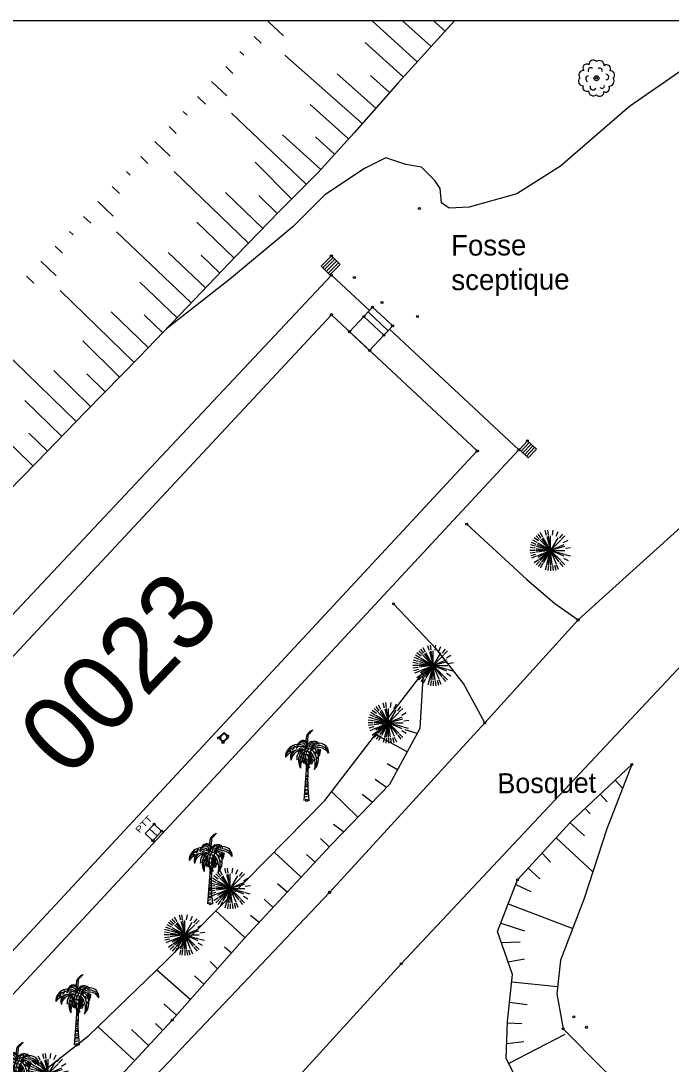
# Model space of a CAD drawing. Extents: x 344013 to 344423, y 298505 to 298795.
# Drawn here: x 344100.8 to 344132.3, y 298741.4 to 298791.9 of the extents above; entities that cross this region are included whole.
import ezdxf

# ---------------------------------------------------------------- set-up
doc = ezdxf.new("R2010")
doc.units = 0
for name, color, linetype in [('Default', 7, 'Continuous'), ('DH_CADRE -CARTOUCHE', 7, 'Continuous'), ('DH_CADRE-CARTOUCHE-NORD', 7, 'Continuous'), ('PC_CONCRETE', 7, 'Continuous'), ('PS_BOLT', 7, 'Continuous'), ('PS_CONST', 7, 'Continuous'), ('PS_DIM', 7, 'Continuous'), ('TOPO_COURBE NIVEAU', 7, 'Continuous'), ('TOPO_POINT', 7, 'Continuous'), ('TOPO_TALUS-TERRAIN NATUREL', 7, 'Continuous'), ('VOIRIE_BORDURE', 7, 'Continuous'), ('VOIRIE_ESPACE VERT', 7, 'Continuous')]:
    doc.layers.add(name, color=color, linetype=linetype)

# ---------------------------------------------------------------- blocks, each defined once
blk = doc.blocks.new('CT2')
at = {"layer": 'Default'}
blk.add_lwpolyline([(0, 0), (1, 0), (1, 1), (0, 1)], close=True, dxfattribs=at)
blk.add_lwpolyline([(0.5, 1), (0.5, 0)], dxfattribs=at)
blk.add_text('PTT', height=0.6, dxfattribs=at).set_placement((-0.3, 1.425))
blk = doc.blocks.new('REG_INC')
at = {"layer": 'Default'}
for p, q in [((0, 1), (1, 1)), ((0, 0), (0, 1)), ((1, 0), (0, 0)), ((1, 1), (1, 0))]:
    blk.add_line(p, q, dxfattribs=at)
for start, end in [(135.0055, 180.0055), (180.0066, 225.0066), (90.0058, 135.0058), (225.0069, 270.0069), (45.0069, 90.0069), (270.0058, 315.0058), (0.0066, 45.0066), (315.0055, 0.0055)]:
    blk.add_arc((0.5, 0.5), 0.44, start, end, dxfattribs=at)
blk = doc.blocks.new('R5')
at = {"layer": 'Default'}
for p, q in [((0, 1), (0, 0)), ((1, 1), (0, 1)), ((0.2, 1), (0.2, 0)), ((0.4, 1), (0.4, 0)), ((0.6, 1), (0.6, 0)), ((0.8, 1), (0.8, 0)), ((1, 0), (1, 1)), ((0, 0), (1, 0)), ((0.6, 0), (0.6, 0))]:
    blk.add_line(p, q, dxfattribs=at)
blk = doc.blocks.new('POINT_DISPLAY')
at = {"layer": 'Default'}
blk.add_circle((0, 0), 0.05, dxfattribs=at)
blk = doc.blocks.new('COCO')
at = {"layer": 'Default'}
for p, q in [((-0.037, 1.06), (0.056, 1.071)), ((0.058, 1.14), (-0.03, 1.162)), ((-0.026, 1.226), (0.061, 1.212)), ((-0.062, 0.537), (0.046, 0.552)), ((0.047, 0.655), (-0.058, 0.642)), ((-0.046, 0.891), (0.052, 0.927)), ((0.054, 0.998), (-0.041, 0.985)), ((0.046, 0.033), (-0.076, 0.051)), ((-0.073, 0.17), (0.045, 0.209)), ((0.045, 0.292), (-0.07, 0.288)), ((-0.068, 0.371), (0.045, 0.374)), ((0.045, 0.47), (-0.065, 0.453))]:
    blk.add_line(p, q, dxfattribs=at)
for points in [[(0.029, 2.551), (-0.016, 2.896), (0.002, 3.125), (0.059, 3.241), (0.173, 3.348), (0.189, 3.356), (0.282, 3.415), (0.266, 3.373), (0.2, 3.318), (0.143, 3.247), (0.093, 3.2), (0.081, 3.165), (0.057, 3.133), (0.057, 3.099), (0.06, 3.037), (0.039, 2.989), (0.039, 2.944), (0.049, 2.877), (0.037, 2.841), (0.013, 2.736)], [(-0.746, 2.559), (-0.864, 2.483)], [(-0.607, 2.534), (-0.704, 2.443)], [(-0.636, 2.639), (-0.541, 2.608)], [(-0.421, 2.58), (-0.503, 2.523)], [(-0.487, 2.68), (-0.386, 2.65)], [(-0.256, 2.553), (-0.385, 2.508)], [(0.013, 2.736), (0.036, 2.813), (0.046, 2.746)], [(0.133, 2.608), (0.185, 2.634)], [(0.196, 2.687), (0.323, 2.715)], [(0.283, 2.765), (0.331, 2.786)], [(-0.77, 2.413), (-0.836, 2.333)], [(-0.183, 2.493), (-0.348, 2.417), (-0.401, 2.307), (-0.448, 2.203), (-0.471, 2.086), (-0.474, 2.023), (-0.466, 1.973), (-0.455, 2.054), (-0.451, 2.146), (-0.387, 2.292), (-0.351, 2.354), (-0.284, 2.404), (-0.233, 2.445), (-0.012, 2.495)], [(-0.276, 2.151), (-0.329, 2.086)], [(-0.203, 2.314), (-0.274, 2.258)], [(-0.23, 2.152), (-0.237, 2.043)], [(-0.161, 2.218), (-0.158, 2.122)], [(-0.059, 2.024), (-0.083, 1.998)], [(-0.04, 2.247), (-0.081, 2.179)], [(0.015, 2.414), (-0.056, 2.352)], [(-0.025, 2.032), (0.002, 1.954)], [(0.022, 2.24), (0.043, 2.13)], [(0.081, 2.404), (0.106, 2.299)], [(0.385, 2.37), (0.469, 2.254)], [(0.473, 2.115), (0.509, 2.012)], [(-0.321, 1.997), (-0.364, 1.9)], [(-0.055, 0.716), (0.048, 0.717), (0.049, 0.787), (-0.051, 0.795)]]:
    blk.add_lwpolyline(points, dxfattribs=at)
for centre, radius in [((-0.144, 1.978), 0.0616), ((-0.187, 1.897), 0.0384), ((-0.124, 1.896), 0.0376), ((-0.11, 1.84), 0.0471), ((0.134, 1.862), 0.0549), ((0.208, 1.822), 0.0626), ((0.254, 1.938), 0.0628)]:
    blk.add_circle(centre, radius, dxfattribs=at)
for centre, radius, start, end in [((-0.427, 2.113), 0.595, 43.6121, 181.4625), ((-0.38, 1.964), 0.648, 57.9192, 166.6201), ((-0.123, 2.59), 0.323, 122.3475, 158.7636), ((-0.199, 2.618), 0.238, 4.5218, 154.101), ((-0.252, 2.556), 0.231, 4.2441, 134.2103), ((-0.16, 2.647), 0.255, 21.0861, 122.3475), ((0.376, 2.508), 0.372, 113.7681, 175.3309), ((0.376, 2.508), 0.372, 113.7681, 175.3309), ((0.418, 2.527), 0.326, 97.1248, 183.9512), ((1.025, 2.053), 0.958, 126.6858, 153.1664), ((0.59, 2.015), 0.548, 29.5654, 139.3517), ((-0.341, 1.9), 0.828, 46.9767, 50.1231), ((0.618, 2.316), 0.451, 356.1627, 159.0009), ((0.609, 2.187), 0.468, 12.1077, 148.3146), ((0.344, 2.407), 0.451, 69.0817, 104.862), ((-0.157, 2.027), 0.74, 51.2475, 54.5217), ((-1.005, 1.577), 1.786, 37.5668, 40.5156), ((-0.254, 2.28), 0.869, 28.4725, 37.0965), ((0.493, 2.767), 0.0679, 35.3205, 126.6858), ((-0.054, 2.379), 0.738, 25.8194, 35.3205), ((-0.291, 1.543), 0.918, 76.7389, 142.8025), ((-0.3, 2.12), 0.482, 151.1331, 199.5942), ((-0.196, 1.874), 0.565, 78.514, 171.3504), ((-0.32, 2.055), 0.433, 119.0834, 188.7621), ((0.362, 1.922), 0.754, 136.7113, 208.8221), ((0.551, 1.79), 0.879, 137.733, 194.3716), ((0.649, 1.599), 0.949, 145.5146, 182.4528), ((0.62, 2.159), 0.753, 153.0868, 230.1124), ((0.659, 2.068), 0.718, 142.3554, 222.2794), ((-0.007, 2.465), 0.0563, 81.7475, 144.3035), ((-0.189, 1.21), 1.324, 71.3715, 81.7475), ((0.294, 2.595), 0.256, 198.6765, 199.7627), ((0.963, 1.939), 0.9, 143.9866, 203.4288), ((0.544, 1.816), 0.474, 137.1953, 172.8987), ((0.308, 2.014), 0.226, 121.4297, 182.29), ((27.302, 0.106), 27.266, 175.4791, 176.5597), ((0.311, 2.152), 0.219, 141.856, 191.5175), ((0.372, 1.847), 0.277, 133.5956, 173.487), ((0.242, 1.964), 0.147, 110.9727, 165.9756), ((0.404, 1.878), 0.354, 125.0585, 146.3893), ((0.398, 2.098), 0.301, 136.4569, 162.0685), ((0.357, 2.084), 0.244, 133.1184, 172.7534), ((-0.759, 1.958), 0.922, 344.8505, 15.8988), ((-0.404, 2.045), 0.619, 329.4666, 26.6793), ((-0.289, 2.11), 0.564, 317.8279, 12.3386), ((-0.543, 1.744), 0.96, 344.8781, 41.1461), ((-0.341, 1.9), 0.828, 334.0687, 41.194), ((-0.157, 2.027), 0.74, 315.1472, 39.0239), ((-1.704, 1.849), 2.327, 7.5978, 16.3666), ((-0.254, 2.28), 0.869, 350.8883, 14.7063), ((-0.482, 2.552), 1.161, 339.3597, 356.5925), ((-85.428, 7.294), 85.622, 355.11326, 356.26352), ((-0.279, 1.637), 0.281, 2.1499, 36.6325), ((-0.265, 1.505), 0.316, 339.9997, 25.7228), ((0.199, 1.66), 0.176, 166.9443, 185.5966), ((0.808, 1.542), 0.777, 142.2358, 156.28)]:
    blk.add_arc(centre, radius, start, end, dxfattribs=at)
blk.add_ellipse((27.425, 0.272), major_axis=(-27.371, 0.966), ratio=0.529859, start_param=6.255729, end_param=6.369141, dxfattribs=at)
blk = doc.blocks.new('ARB1')
at = {"layer": 'Default'}
blk.add_circle((0, 0), 0.122, dxfattribs=at)
for centre, radius, start, end in [((-0.471, 0.503), 0.183, 53.9554, 222.2066), ((-0.153, 0.664), 0.211, 43.6925, 183.5969), ((0.139, 0.613), 0.241, 358.4583, 125.1928), ((0.501, 0.468), 0.183, 325.1444, 131.0175), ((-0.613, 0.139), 0.241, 88.4583, 215.1928), ((-0.373, -0.024), 0.149, 103.7092, 242.3465), ((-0.276, 0.37), 0.134, 52.4396, 209.5496), ((0.164, 0.38), 0.112, 330.5895, 133.7127), ((0.458, 0.052), 0.137, 276.6214, 88.967), ((0.613, -0.139), 0.241, 268.4583, 35.1928), ((0.664, 0.153), 0.211, 313.6925, 93.5969), ((-0.664, -0.153), 0.211, 133.6925, 273.5969), ((-0.478, -0.443), 0.19, 155.2243, 300.9377), ((-0.163, -0.42), 0.148, 159.5371, 338.1663), ((0.271, -0.38), 0.112, 210.5895, 13.7127), ((0.448, -0.483), 0.188, 243.1323, 33.0297), ((-0.139, -0.613), 0.241, 178.4583, 305.1928), ((0.153, -0.664), 0.211, 223.6925, 3.5969)]:
    blk.add_arc(centre, radius, start, end, dxfattribs=at)
blk = doc.blocks.new('ARB2')
at = {"layer": 'Default'}
for p, q in [((-0.575, 0.453), (-0.775, 0.605)), ((-0.513, 0.525), (-0.688, 0.702)), ((-0.438, 0.589), (-0.588, 0.786)), ((-0.356, 0.642), (-0.481, 0.858)), ((-0.181, 0.716), (-0.244, 0.956)), ((-0.088, 0.736), (-0.119, 0.983)), ((0.106, 0.736), (0.144, 0.983)), ((0.287, 0.684), (0.388, 0.914)), ((0.456, 0.589), (0.612, 0.786)), ((0.531, 0.525), (0.706, 0.702)), ((-0.731, 0), (-0.981, 0)), ((-0.725, 0.1), (-0.969, 0.133)), ((-0.706, 0.195), (-0.944, 0.259)), ((-0.675, 0.286), (-0.9, 0.381)), ((-0.631, 0.373), (-0.844, 0.497)), ((0.65, 0.373), (0.862, 0.497)), ((0.744, 0.1), (0.987, 0.133)), ((-0.725, -0.1), (-0.969, -0.133)), ((-0.706, -0.195), (-0.944, -0.259)), ((-0.675, -0.287), (-0.9, -0.383)), ((-0.575, -0.455), (-0.775, -0.605)), ((0.65, -0.373), (0.862, -0.498)), ((0.725, -0.195), (0.963, -0.259)), ((-0.513, -0.527), (-0.688, -0.702)), ((-0.438, -0.591), (-0.588, -0.787)), ((-0.356, -0.644), (-0.481, -0.859)), ((-0.181, -0.717), (-0.244, -0.956)), ((-0.088, -0.737), (-0.119, -0.983)), ((0.013, -0.741), (0.013, -0.989)), ((0.106, -0.737), (0.144, -0.983)), ((0.2, -0.717), (0.263, -0.956)), ((0.287, -0.686), (0.388, -0.916)), ((0.456, -0.591), (0.612, -0.787)), ((0.531, -0.527), (0.706, -0.702))]:
    blk.add_line(p, q, dxfattribs=at)
for points in [[(-0.688, 0.091), (0.013, 0), (-0.338, 0.608)], [(-0.419, 0.556), (0.013, 0), (-0.638, 0.269)], [(-0.169, 0.677), (0.013, 0), (-0.6, 0.35)], [(0.013, 0.008), (0.013, 0), (-0.081, 0.695)], [(0.362, 0.608), (0.013, 0), (0.013, 0.702)], [(-0.487, -0.497), (0.013, 0), (-0.694, 0)], [(-0.638, -0.269), (0.013, 0), (-0.688, -0.092)], [(-0.487, 0.495), (0.013, 0), (-0.669, 0.181)], [(-0.169, -0.678), (0.013, 0), (-0.6, -0.352)], [(-0.544, -0.428), (0.013, 0), (-0.338, -0.608)], [(-0.081, -0.695), (0.013, 0), (-0.419, -0.558)], [(0.013, -0.702), (0.013, 0), (0, 0)], [(0.656, 0.269), (0.013, 0), (0.506, 0.495)], [(0.688, 0.181), (0.013, 0), (0.713, 0)], [(0.438, -0.558), (0.013, 0), (0.656, -0.269)], [(0.506, -0.497), (0.013, 0), (0.688, -0.181)], [(0.1, -0.695), (0.013, 0), (0.281, -0.648)], [(0.019, 0), (0.013, 0), (0.013, -0.009)]]:
    blk.add_lwpolyline(points, dxfattribs=at)

msp = doc.modelspace()

# ---------------------------------------------------------------- linework, layer by layer
at = {"layer": 'DH_CADRE -CARTOUCHE'}
for points in [[(344012.906, 298504.876), (344422.906, 298504.876), (344422.906, 298791.876), (344012.906, 298791.876)], [(344115.797, 298777.646), (344091.09, 298751.159), (344098.189, 298744.522), (344122.865, 298771.047)]]:
    msp.add_lwpolyline(points, close=True, dxfattribs=at)
at = {"layer": 'PS_BOLT'}
msp.add_lwpolyline([(344117.636, 298777.85), (344115.797, 298779.561), (344089.042, 298751.089), (344098.26, 298742.47), (344124.879, 298771.11), (344118.609, 298776.944)], dxfattribs=at)
at = {"layer": 'PS_DIM'}
for points in [[(344117.367, 298777.561), (344117.792, 298778.016), (344118.765, 298777.111), (344118.338, 298776.654)], [(344118.543, 298776.873), (344117.582, 298777.791)]]:
    msp.add_lwpolyline(points, dxfattribs=at)
msp.add_lwpolyline([(344117.65, 298775.917), (344118.338, 298776.654), (344117.367, 298777.561), (344116.678, 298776.824)], close=True, dxfattribs=at)
at = {"layer": 'TOPO_COURBE NIVEAU'}
msp.add_lwpolyline([(344133.015, 298789.642), (344130.234, 298787.735), (344126.894, 298784.84), (344124.777, 298783.498), (344122.469, 298782.862), (344121.507, 298782.799), (344121.123, 298783.057), (344121.06, 298783.762), (344120.804, 298784.147), (344120.164, 298784.789), (344119.395, 298784.918), (344118.434, 298785.241), (344117.408, 298784.73), (344115.484, 298783.452), (344113.943, 298781.916), (344110.863, 298779.358), (344107.81, 298776.961)], dxfattribs=at)
at = {"layer": 'TOPO_TALUS-TERRAIN NATUREL'}
for p, q in [((344112.743, 298791.846), (344113.476, 298791.153)), ((344119.957, 298789.889), (344117.766, 298791.876)), ((344120.629, 298790.63), (344119.249, 298791.876)), ((344121.3, 298791.372), (344120.74, 298791.876)), ((344112.056, 298791.119), (344112.404, 298790.79)), ((344111.369, 298790.391), (344111.553, 298790.218)), ((344119.285, 298789.148), (344117.432, 298790.828)), ((344117.292, 298786.905), (344113.548, 298790.22)), ((344110.682, 298789.664), (344111.032, 298789.334)), ((344109.996, 298788.937), (344110.733, 298788.241)), ((344117.955, 298787.654), (344116.083, 298789.311)), ((344118.618, 298788.402), (344117.687, 298789.237)), ((344109.309, 298788.21), (344109.698, 298787.842)), ((344116.626, 298786.159), (344114.763, 298787.827)), ((344108.622, 298787.482), (344108.807, 298787.308)), ((344114.582, 298783.963), (344110.962, 298787.414)), ((344107.935, 298786.755), (344108.286, 298786.424)), ((344115.282, 298784.677), (344113.429, 298786.356)), ((344107.249, 298786.028), (344107.989, 298785.329)), ((344115.954, 298785.418), (344115.027, 298786.257)), ((344106.562, 298785.301), (344106.911, 298784.967)), ((344113.873, 298783.256), (344112.108, 298785.027)), ((344105.871, 298784.577), (344106.055, 298784.401)), ((344111.777, 298781.11), (344108.181, 298784.586)), ((344105.18, 298783.854), (344105.53, 298783.52)), ((344112.472, 298781.829), (344110.674, 298783.567)), ((344113.167, 298782.548), (344112.276, 298783.425)), ((344104.489, 298783.131), (344105.228, 298782.425)), ((344103.798, 298782.407), (344104.149, 298782.072)), ((344111.082, 298780.39), (344109.278, 298782.122)), ((344103.108, 298781.684), (344103.293, 298781.507)), ((344109.012, 298778.217), (344105.391, 298781.667)), ((344102.417, 298780.96), (344102.768, 298780.625)), ((344101.726, 298780.237), (344102.468, 298779.528)), ((344109.702, 298778.942), (344107.892, 298780.667)), ((344110.392, 298779.666), (344109.487, 298780.528)), ((344101.035, 298779.513), (344101.387, 298779.177)), ((344108.321, 298777.494), (344106.513, 298779.222)), ((344106.241, 298775.331), (344102.654, 298778.816)), ((344106.937, 298776.05), (344105.131, 298777.779)), ((344107.629, 298776.772), (344106.726, 298777.637)), ((344105.539, 298774.618), (344103.758, 298776.374)), ((344103.438, 298772.476), (344099.857, 298775.967)), ((344104.135, 298773.194), (344102.354, 298774.949)), ((344104.837, 298773.906), (344103.947, 298774.784)), ((344102.744, 298771.756), (344100.944, 298773.492)), ((344101.352, 298770.319), (344099.563, 298772.066)), ((344102.049, 298771.036), (344101.149, 298771.904)), ((344120.189, 298759.325), (344120.154, 298759.327)), ((344120.13, 298758.327), (344120.109, 298758.328)), ((344119.95, 298757.363), (344119.374, 298757.543)), ((344119.472, 298756.484), (344117.94, 298757.319)), ((344118.993, 298755.606), (344118.491, 298755.892)), ((344130.269, 298755.79), (344130.285, 298755.772)), ((344118.472, 298754.759), (344117.917, 298755.133)), ((344129.539, 298755.105), (344129.885, 298754.737)), ((344117.082, 298753.319), (344115.811, 298754.548)), ((344117.777, 298754.039), (344117.294, 298754.407)), ((344128.81, 298754.421), (344129.153, 298754.055)), ((344128.081, 298753.736), (344128.329, 298753.471)), ((344116.388, 298752.6), (344115.902, 298752.955)), ((344127.352, 298753.051), (344128.049, 298752.411)), ((344115.695, 298751.878), (344115.266, 298752.284)), ((344126.676, 298752.314), (344128.465, 298750.67)), ((344114.335, 298750.411), (344113.022, 298751.628)), ((344115.015, 298751.144), (344114.585, 298751.504)), ((344125.999, 298751.577), (344126.408, 298751.138)), ((344125.322, 298750.84), (344125.884, 298750.325)), ((344113.655, 298749.677), (344113.19, 298750.082)), ((344124.722, 298750.057), (344125.449, 298749.719)), ((344112.975, 298748.944), (344112.549, 298749.341)), ((344124.362, 298749.123), (344127.485, 298747.92)), ((344111.615, 298747.477), (344110.204, 298748.785)), ((344112.295, 298748.21), (344111.874, 298748.553)), ((344124.002, 298748.19), (344125.155, 298747.805)), ((344110.952, 298746.728), (344110.62, 298747.021)), ((344124.029, 298747.25), (344124.946, 298747.275)), ((344124.359, 298746.306), (344125.155, 298746.455)), ((344108.964, 298744.479), (344107.335, 298745.919)), ((344110.289, 298745.978), (344109.93, 298746.325)), ((344109.627, 298745.229), (344109.173, 298745.63)), ((344124.536, 298745.344), (344126.749, 298745.109)), ((344108.302, 298743.73), (344107.681, 298744.279)), ((344124.43, 298744.349), (344125.274, 298744.24)), ((344124.329, 298743.354), (344125.021, 298743.324)), ((344106.266, 298741.525), (344104.515, 298743.151)), ((344106.947, 298742.258), (344106.115, 298743.03)), ((344107.627, 298742.991), (344107.272, 298743.321)), ((344124.286, 298742.355), (344125.123, 298742.46)), ((344124.382, 298741.386), (344127.118, 298742.804))]:
    msp.add_line(p, q, dxfattribs=at)
for points in [[(344121.753, 298791.876), (344121.111, 298791.163), (344119.03, 298788.868), (344116.896, 298786.457), (344115.138, 298784.518), (344113.279, 298782.664), (344111.206, 298780.52), (344108.818, 298778.013), (344106.507, 298775.601), (344103.883, 298772.937), (344101.54, 298770.509), (344099.419, 298768.364), (344096.952, 298765.905), (344094.398, 298763.595), (344092.09, 298761.545), (344089.727, 298759.519), (344087.268, 298757.305), (344084.81, 298755.059), (344082.763, 298753.38), (344080.951, 298751.951), (344079.878, 298751.292)], [(344093.796, 298737.849), (344096.039, 298738.089), (344100.001, 298739.57), (344104.057, 298742.749), (344107.776, 298746.346), (344111.679, 298750.267), (344115.483, 298754.122), (344120.249, 298760.324)], [(344120.249, 298760.324), (344120.087, 298757.616), (344118.611, 298754.904), (344115.791, 298751.982), (344111.589, 298747.448), (344108.09, 298743.49), (344104.387, 298739.501), (344101.668, 298736.664), (344099.652, 298735.174), (344097.999, 298734.955), (344096.528, 298735.517), (344095.327, 298736.328), (344093.796, 298737.849)], [(344146.792, 298719.679), (344146.928, 298720.992), (344146.442, 298722.409), (344144.219, 298724.371), (344141.652, 298726.758), (344138.951, 298729.169), (344136.242, 298731.476), (344134.201, 298733.13), (344131.821, 298735.077), (344129.756, 298736.567), (344127.823, 298737.923), (344126.636, 298738.844), (344125.396, 298740.027), (344124.752, 298740.672), (344124.255, 298741.632), (344124.332, 298743.426), (344124.573, 298745.693), (344123.844, 298747.78), (344124.808, 298750.28), (344127.362, 298753.061), (344130.348, 298755.864)], [(344130.348, 298755.864), (344129.139, 298752.757), (344128.047, 298749.375), (344126.893, 298746.388), (344126.71, 298744.759), (344127.026, 298743.068), (344130.916, 298739.136), (344135.968, 298734.808), (344138.904, 298732.255), (344141.857, 298729.875), (344143.823, 298728.108), (344146.055, 298726.342), (344147.327, 298725.192), (344148.161, 298724.497), (344148.568, 298723.821), (344148.724, 298723.034), (344148.613, 298722.231), (344148.361, 298721.682), (344147.974, 298721.092), (344146.792, 298719.679)]]:
    msp.add_lwpolyline(points, dxfattribs=at)
at = {"layer": 'VOIRIE_BORDURE'}
for points in [[(344012.906, 298718.231), (344022.459, 298709.623), (344035.4, 298697.966), (344038.262, 298695.856), (344041.267, 298693.813), (344044.479, 298691.842), (344047.664, 298690.365), (344050.648, 298689.339), (344052.822, 298689.099), (344054.599, 298689.128), (344056.124, 298689.428), (344057.609, 298690.129), (344058.956, 298690.85), (344060.299, 298691.725), (344061.274, 298692.556), (344063.092, 298694.498), (344091.5, 298724.03), (344099.786, 298732.889), (344115.711, 298749.674), (344123.231, 298757.884), (344127.749, 298762.864), (344141.666, 298775.429), (344153.501, 298787.287)], [(344122.349, 298767.504), (344125.245, 298764.839), (344126.615, 298763.656), (344127.749, 298762.864)], [(344123.231, 298757.884), (344122.198, 298759.793), (344120.893, 298761.451), (344118.804, 298763.646)], [(344135.251, 298763.339), (344119.175, 298746.216), (344104.333, 298729.921), (344103.629, 298728.425), (344103.178, 298726.908), (344102.994, 298725.349), (344103.009, 298724.152), (344103.293, 298722.366), (344103.622, 298721.156), (344104.336, 298719.642), (344105.154, 298718.475), (344128.542, 298697.099), (344156.76, 298672.229)]]:
    msp.add_lwpolyline(points, dxfattribs=at)

# ---------------------------------------------------------------- block references
at = {"layer": 'DH_CADRE-CARTOUCHE-NORD', "xscale": 0.6282348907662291, "yscale": 0.5009724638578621, "rotation": 46.81817999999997}
msp.add_blockref('CT2', (344107.146, 298752.177), dxfattribs=at)
at = {"layer": 'PC_CONCRETE'}
for name, p, xscale, yscale, rotation in [('R5', (344115.797, 298780.499), 0.597969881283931, -0.703915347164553, -45.02996999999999), ('R5', (344125.294, 298771.538), 0.597167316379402, -0.5722405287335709, -43.38585000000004), ('REG_INC', (344110.333, 298757.161), 0.317396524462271, 0.37762918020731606, -46.69956)]:
    msp.add_blockref(name, p, dxfattribs=dict(at, xscale=xscale, yscale=yscale, rotation=rotation))
at = {"layer": 'TOPO_POINT'}
for p in [(344128.635, 298789.099), (344120.058, 298782.794), (344115.797, 298780.499), (344115.797, 298779.561), (344116.909, 298779.447), (344118.246, 298778.242), (344115.797, 298777.646), (344117.792, 298778.016), (344117.367, 298777.561), (344119.964, 298777.557), (344116.678, 298776.824), (344118.338, 298776.654), (344118.765, 298777.111), (344117.65, 298775.917), (344124.879, 298771.11), (344125.294, 298771.538), (344122.865, 298771.047), (344122.349, 298767.504), (344126.396, 298766.236), (344118.804, 298763.646), (344127.749, 298762.864), (344120.716, 298760.664), (344118.555, 298757.883), (344123.231, 298757.884), (344110.333, 298757.161), (344110.764, 298757.255), (344110.551, 298756.931), (344130.348, 298755.864), (344114.598, 298754.124), (344107.211, 298752.978), (344107.576, 298752.635), (344107.146, 298752.177), (344110.885, 298749.866), (344124.808, 298750.28), (344115.711, 298749.674), (344109.929, 298749.121), (344108.681, 298747.61), (344119.175, 298746.216), (344108.09, 298743.49), (344127.539, 298743.651), (344127.026, 298743.068), (344128.149, 298743.139), (344103.473, 298742.285)]:
    msp.add_blockref('POINT_DISPLAY', p, dxfattribs=at)
at = {"layer": 'VOIRIE_ESPACE VERT'}
for name, p in [('ARB1', (344128.635, 298789.099)), ('ARB2', (344126.396, 298766.236)), ('ARB2', (344120.716, 298760.664)), ('ARB2', (344118.555, 298757.883)), ('COCO', (344114.598, 298754.124)), ('COCO', (344109.929, 298749.121)), ('ARB2', (344110.885, 298749.866)), ('ARB2', (344108.681, 298747.61)), ('COCO', (344103.473, 298742.285)), ('COCO', (344100.566, 298738.997)), ('ARB2', (344102.073, 298740.891))]:
    msp.add_blockref(name, p, dxfattribs=at)

# ---------------------------------------------------------------- texts
at = {"layer": 'PS_CONST'}
for s, height, rotation, p in [('Fosse', 1.0003, 0.3665, (344121.598, 298780.501)), ('sceptique', 1.0003, 0.3665, (344121.609, 298778.834)), ('0023', 3.662, 46.2269, (344103.027, 298755.116)), ('Bosquet', 0.9758, 0.3665, (344123.837, 298754.468))]:
    msp.add_text(s, height=height, rotation=rotation, dxfattribs=at).set_placement(p)

doc.saveas('drawing.dxf')
